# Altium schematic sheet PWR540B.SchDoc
size 431 x 279 mm; Date: Not shown in title block; ApprovedBy: Not shown in title block; CheckedBy: Not shown in title block; Author: Not shown in title block; CompanyName: Not shown in title block; Engineer: Not shown in title block; Organization: Not shown in title block; Address1: Not shown in title block; Address2: Not shown in title block; Address3: Not shown in title block; Address4: Not shown in title block; DocumentNumber: 1; Revision: Use project parameter SCH_Rev; SheetNumber: 1; SheetTotal: 2; PageSetup: Record=PageOptions¦CenterHorizontal=True¦CenterVertical=True¦PrintScale=0.64¦XCorrection=1.00¦YCorrection=1.00¦PrintKind=0¦BorderSize=5000000¦LeftOffset=0¦BottomOffset=0¦Orientation=2¦PaperLength=1000¦PaperWidth=1000¦Scale=100¦PaperSource=15¦PrintQuality=600¦MediaType=1¦DitherType=10¦PaperKind=Letter¦PrintScaleMode=1
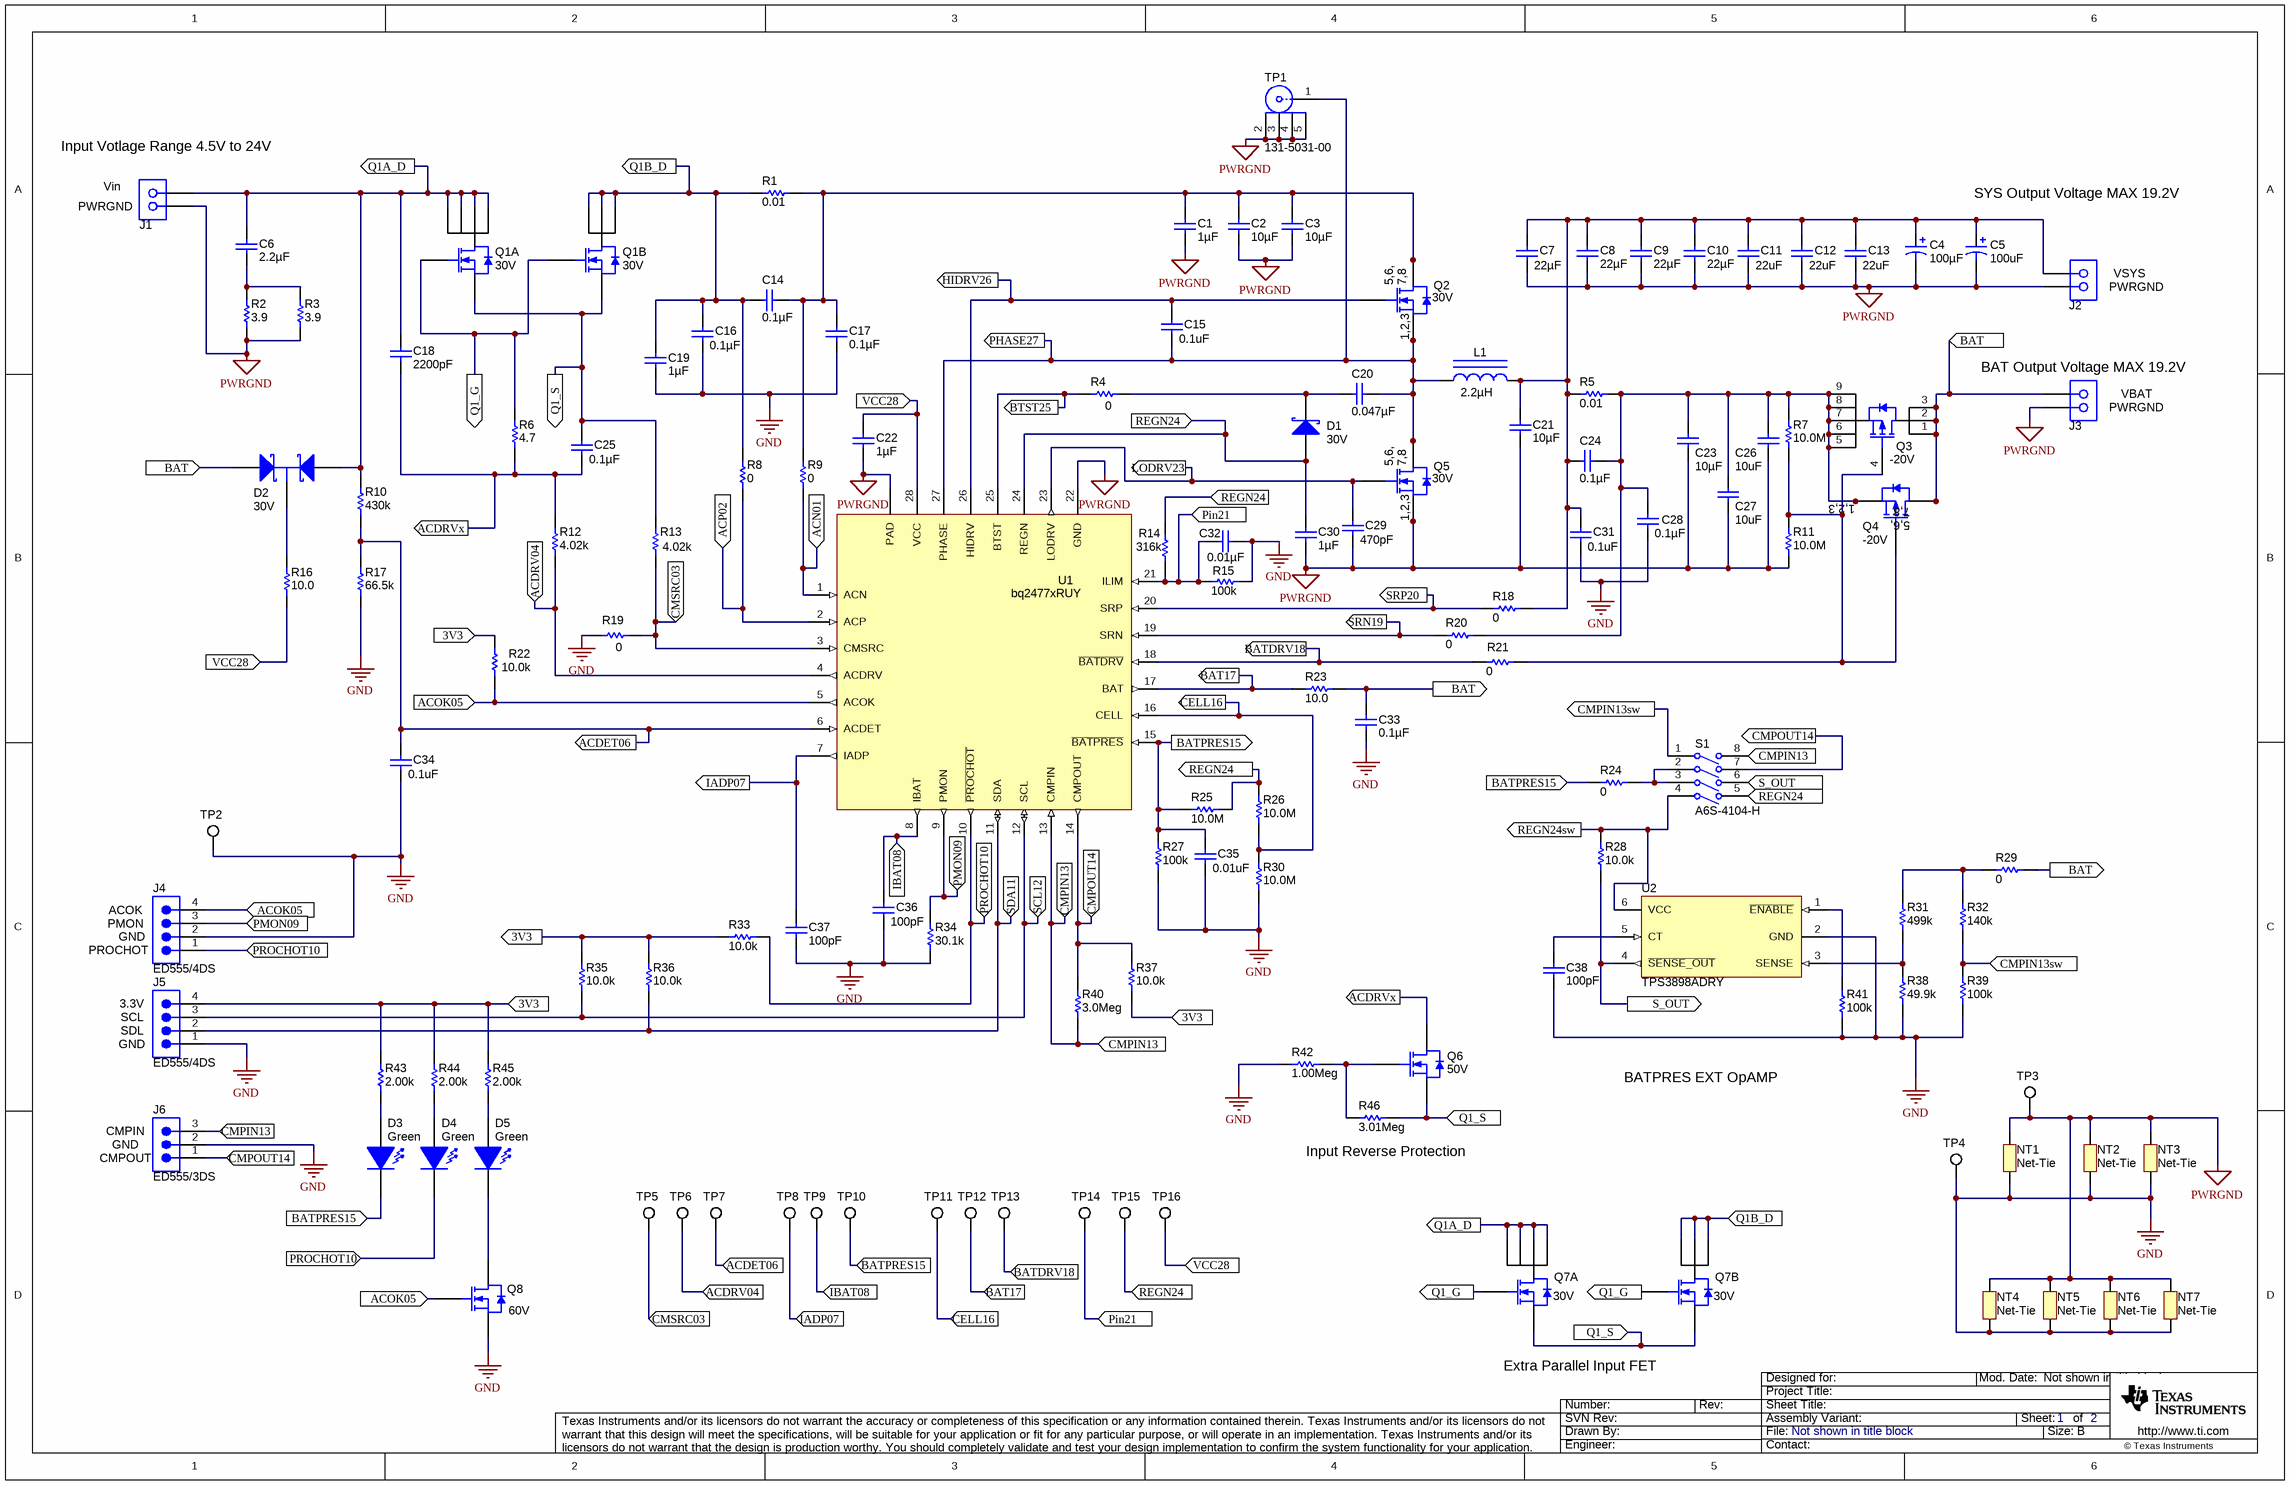
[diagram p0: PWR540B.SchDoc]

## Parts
C1  ValueDisplayed: 1µF  [0603L]  (hidden comment: GRM188R71E105KA12D)
C2  ValueDisplayed: 10µF  [1206]  (hidden comment: GRM31CR61E106KA12L)
C3  ValueDisplayed: 10µF  [1206]  (hidden comment: GRM31CR61E106KA12L)
C4  ValueDisplayed: 100µF  [SM_RADIAL_8MM]  (hidden comment: 20SVP100M)
C5  value 100uF  [SM_RADIAL_10AMM]  (hidden comment: 16SVP100M)
C6  ValueDisplayed: 2.2µF  [1206]  (hidden comment: GRM31MR71E225KA93L)
C7  ValueDisplayed: 22µF  [1210]  (hidden comment: GRM32ER61E226KE15L)
C8  ValueDisplayed: 22µF  [1210]  (hidden comment: GRM32ER61E226KE15L)
C9  ValueDisplayed: 22µF  [1210]  (hidden comment: GRM32ER61E226KE15L)
C10  ValueDisplayed: 22µF  [1210]  (hidden comment: GRM32ER61E226KE15L)
C11  value 22uF  [1210]  (hidden comment: GRM32ER61E226KE15L)
C12  value 22uF  [1210]  (hidden comment: GRM32ER61E226KE15L)
C13  value 22uF  [1210]  (hidden comment: GRM32ER61E226KE15L)
C14  ValueDisplayed: 0.1µF  [0603L]  (hidden comment: GRM188R71E104KA01D)
C15  value 0.1uF  [0603L]  (hidden comment: GRM188R71E104KA01D)
C16  ValueDisplayed: 0.1µF  [0603L]  (hidden comment: GRM188R71E104KA01D)
C17  ValueDisplayed: 0.1µF  [0603L]  (hidden comment: GRM188R71E104KA01D)
C18  ValueDisplayed: 2200pF  [0603L]  (hidden comment: GRM188R71E222KA01D)
C19  ValueDisplayed: 1µF  [0603L]  (hidden comment: GRM188R71E105KA12D)
C20  ValueDisplayed: 0.047µF  [0603L]  (hidden comment: GRM188R71E473KA01D)
C21  ValueDisplayed: 10µF  [1206]  (hidden comment: GRM31CR61E106KA12L)
C22  ValueDisplayed: 1µF  [0603L]  (hidden comment: GRM188R71E105KA12D)
C23  ValueDisplayed: 10µF  [1206]  (hidden comment: GRM31CR61E106KA12L)
C24  ValueDisplayed: 0.1µF  [0603L]  (hidden comment: GRM188R71E104KA01D)
C25  ValueDisplayed: 0.1µF  [0603L]  (hidden comment: GRM188R71E104KA01D)
C26  value 10uF  [1206]  (hidden comment: GRM31CR61E106KA12L)
C27  value 10uF  [1206]  (hidden comment: GRM31CR61E106KA12L)
C28  ValueDisplayed: 0.1µF  [0603L]  (hidden comment: GRM188R71E104KA01D)
C29  ValueDisplayed: 470pF  [0603L]  (hidden comment: GRM1885C1H471JA01D)
C30  ValueDisplayed: 1µF  [0603]  (hidden comment: GRM188R71E105KA12D)
C31  value 0.1uF  [0603L]  (hidden comment: GRM188R71E104KA01D)
C32  ValueDisplayed: 0.01µF  [0603]  (hidden comment: GRM188R71E103KA01D)
C33  ValueDisplayed: 0.1µF  [0603L]  (hidden comment: GRM188R71E104KA01D)
C34  value 0.1uF  [0603L]  (hidden comment: GRM188R71E104KA01D)
C35  value 0.01uF  [0603]  (hidden comment: GRM188R71E103KA01D)
C36  ValueDisplayed: 100pF  [0603L]  (hidden comment: C0603C101J5GAC)
C37  ValueDisplayed: 100pF  [0603L]  (hidden comment: C0603C101J5GAC)
C38  ValueDisplayed: 100pF  [0603L]  (hidden comment: C0603C101J5GAC)
D1  Value2: 30V  [SOT-23]  (hidden comment: BAT54-7-F)
D2  Value2: 30V  [SOT-23]  (hidden comment: BAT54C-7-F)
D3  value Green  [LED_LTST-C190]  (hidden comment: LTST-C190GKT)
D4  value Green  [LED_LTST-C190]  (hidden comment: LTST-C190GKT)
D5  value Green  [LED_LTST-C190]  (hidden comment: LTST-C190GKT)
J1  ED120/2DS  [CONN_ED120-2DS]  (value not drawn)
J2  ED120/2DS  [CONN_ED120-2DS]  (value not drawn)
J3  ED120/2DS  [CONN_ED120-2DS]  (value not drawn)
J4  ED555/4DS  [TERM_BLK_ED555-4DS]
J5  ED555/4DS  [TERM_BLK_ED555-4DS]
J6  ED555/3DS  [TERM_BLK_ED555-3DS]
L1  ValueDisplayed: 2.2µH  [IHLP-3232DZ]  (hidden comment: IHLP3232DZER2R2M01)
NT1  Net-Tie  [Net-Tie_20milWide_60milLong]  (net tie, no BOM)
NT2  Net-Tie  [Net-Tie_20milWide_60milLong]  (net tie, no BOM)
NT3  Net-Tie  [Net-Tie_20milWide_60milLong]  (net tie, no BOM)
NT4  Net-Tie  [Net-Tie_20milWide_60milLong]  (net tie, no BOM)
NT5  Net-Tie  [Net-Tie_20milWide_60milLong]  (net tie, no BOM)
NT6  Net-Tie  [Net-Tie_20milWide_60milLong]  (net tie, no BOM)
NT7  Net-Tie  [Net-Tie_20milWide_60milLong]  (net tie, no BOM)
Q1  value 30V  [TRANS_NexFET_Q3E]  (hidden comment: CSD87312Q3E)  (parts A,B of 2)
Q2  value 30V  [TRANS_NexFET_Q3]  (hidden comment: CSD17308Q3)
Q3  value -20V  [DQG0008A]  (hidden comment: CSD25401Q3)
Q4  value -20V  [PowerPAK_SO-8]  (hidden comment: SI7139DP-T1-GE3)
Q5  value 30V  [TRANS_NexFET_Q3]  (hidden comment: CSD17308Q3)
Q6  value 50V  [SOT-323]  (hidden comment: BSS138W-7-F)
Q7  value 30V  [TRANS_NexFET_Q3E]  (hidden comment: CSD87312Q3E)  (parts A,B of 2)
Q8  value 60V  [SOT-23L]  (hidden comment: 2N7002ET1G)
R1  value 0.01  [1206]  (hidden comment: WSLP1206R0100FEA)
R2  value 3.9  [1206]  (hidden comment: CRCW12063R90JNEA)
R3  value 3.9  [1206]  (hidden comment: CRCW12063R90JNEA)
R4  value 0  [0603L]  (hidden comment: CRCW06030000Z0EA)
R5  value 0.01  [1206]  (hidden comment: WSLP1206R0100FEA)
R6  value 4.7  [0603L]  (hidden comment: CRCW06034R70JNEA)
R7  value 10.0M  [0603L]  (hidden comment: CRCW060310M0JNEA)
R8  value 0  [0603L]  (hidden comment: CRCW06030000Z0EA)
R9  value 0  [0603L]  (hidden comment: CRCW06030000Z0EA)
R10  value 430k  [0603L]  (hidden comment: RC0603FR-07430KL)
R11  value 10.0M  [0603L]  (hidden comment: CRCW060310M0JNEA)
R12  value 4.02k  [0603L]  (hidden comment: CRCW06034K02FKEA)
R13  value 4.02k  [0603L]  (hidden comment: CRCW06034K02FKEA)
R14  value 316k  [0603]  (hidden comment: CRCW0603316KFKEA)
R15  value 100k  [0603]  (hidden comment: CRCW0603100KFKEA)
R16  value 10.0  [1206]  (hidden comment: CRCW120610R0FKEA)
R17  value 66.5k  [0603L]  (hidden comment: CRCW060366K5FKEA)
R18  value 0  [0603L]  (hidden comment: CRCW06030000Z0EA)
R19  value 0  [0603L]  (hidden comment: CRCW06030000Z0EA)
R20  value 0  [0603L]  (hidden comment: CRCW06030000Z0EA)
R21  value 0  [0603L]  (hidden comment: CRCW06030000Z0EA)
R22  value 10.0k  [0603L]  (hidden comment: CRCW060310K0FKEA)
R23  value 10.0  [0603]  (hidden comment: CRCW060310R0FKEA)
R24  value 0  [0805_HV]  (hidden comment: CRCW08050000Z0EA)
R25  value 10.0M  [0603L]  (hidden comment: CRCW060310M0JNEA)
R26  value 10.0M  [0603L]  (hidden comment: CRCW060310M0JNEA)
R27  value 100k  [0603]  (hidden comment: CRCW0603100KFKEA)
R28  value 10.0k  [0603L]  (hidden comment: CRCW060310K0FKEA)
R29  value 0  [0603L]  (hidden comment: CRCW06030000Z0EA)
R30  value 10.0M  [0603L]  (hidden comment: CRCW060310M0JNEA)
R31  value 499k  [0603L]  (hidden comment: CRCW0603499KFKEA)
R32  value 140k  [0603L]  (hidden comment: CRCW0603140KFKEA)
R33  value 10.0k  [0603L]  (hidden comment: CRCW060310K0FKEA)
R34  value 30.1k  [0603]  (hidden comment: CRCW060330K1FKEA)
R35  value 10.0k  [0603L]  (hidden comment: CRCW060310K0FKEA)
R36  value 10.0k  [0603L]  (hidden comment: CRCW060310K0FKEA)
R37  value 10.0k  [0603L]  (hidden comment: CRCW060310K0FKEA)
R38  value 49.9k  [0603L]  (hidden comment: CRCW060349K9FKEA)
R39  value 100k  [0603L]  (hidden comment: CRCW0603100KFKEA)
R40  value 3.0Meg  [0603L]  (hidden comment: CRCW06033M00JNEA)
R41  value 100k  [0603L]  (hidden comment: CRCW0603100KFKEA)
R42  value 1.00Meg  [0603L]  (hidden comment: CRCW06031M00FKEA)
R43  value 2.00k  [0603L]  (hidden comment: CRCW06032K00FKEA)
R44  value 2.00k  [0603L]  (hidden comment: CRCW06032K00FKEA)
R45  value 2.00k  [0603L]  (hidden comment: CRCW06032K00FKEA)
R46  value 3.01Meg  [0603L]  (hidden comment: CRCW06033M01FKEA)
S1  A6S-4104-H  [SW_A6S-4104-H]
TP1  131-5031-00  [Tek_131-5031-00]
TP2  5015  [Testpoint_Keystone_Miniature]  (value not drawn)
TP3  5015  [Testpoint_Keystone_Miniature]  (value not drawn)
TP4  5015  [Testpoint_Keystone_Miniature]  (value not drawn)
TP5  5015  [Testpoint_Keystone_Miniature]  (value not drawn)
TP6  5015  [Testpoint_Keystone_Miniature]  (value not drawn)
TP7  5015  [Testpoint_Keystone_Miniature]  (value not drawn)
TP8  5015  [Testpoint_Keystone_Miniature]  (value not drawn)
TP9  5015  [Testpoint_Keystone_Miniature]  (value not drawn)
TP10  5015  [Testpoint_Keystone_Miniature]  (value not drawn)
TP11  5015  [Testpoint_Keystone_Miniature]  (value not drawn)
TP12  5015  [Testpoint_Keystone_Miniature]  (value not drawn)
TP13  5015  [Testpoint_Keystone_Miniature]  (value not drawn)
TP14  5015  [Testpoint_Keystone_Miniature]  (value not drawn)
TP15  5015  [Testpoint_Keystone_Miniature]  (value not drawn)
TP16  5015  [Testpoint_Keystone_Miniature]  (value not drawn)
U1  bq2477xRUY  [RUY0028A]
U2  TPS3898ADRY  [DRY0006A]

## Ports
3V3, ACDET06, ACDRV04, ACDRVx, ACN01, ACOK05, ACP02, BAT, BAT17, BATDRV18, BATPRES15, BTST25, CELL16, CMPIN13, CMPIN13sw, CMPOUT14, CMSRC03, HIDRV26, IADP07, IBAT08, LODRV23, PHASE27, Pin21, PMON09, PROCHOT10, Q1_G, Q1_S, Q1A_D, Q1B_D, REGN24, REGN24sw, S_OUT, SCL12, SDA11, SRN19, SRP20, VCC28

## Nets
GND: C16.2 C17.2 C19.2 C28.2 C31.2 C32.1 C33.2 C34.2 C35.2 C36.2 C37.2 C38.2 J4.2 J5.1 J6.2 NT1.1 NT2.1 NT3.1 NT4.1 NT5.1 NT6.1 NT7.1 Q8.2(S) R15.2 R17.1 R19.2 R27.1 R30.1 R34.2 R38.1 R39.1 R41.1 R42.1 TP2.1 TP4.1 U2.2(GND)
PWRGND: C1.2 C2.2 C3.2 C4.2(-) C5.2(-) C7.2 C8.2 C9.2 C10.2 C11.2 C12.2 C13.2 C21.2 C22.2 C23.2 C26.2 C27.2 C29.2 C30.2 J1.2 J2.1 J3.1 NT1.2 NT2.2 NT3.2 NT4.2 NT5.2 NT6.2 NT7.2 Q5.1(S) Q5.2(S) Q5.3(S) R2.1 R3.1 R11.1 TP1.2 TP1.3 TP1.4 TP1.5 TP3.1 U1.22(GND) U1.29(PAD)
3V3: J5.4 R22.2 R33.2 R35.2 R36.2 R37.1 R43.1 R44.1 R45.2 ; port 3V3
ACDET06: C34.1 R10.1 R17.2 TP7.1 U1.6(ACDET) ; port ACDET06
ACDRV04: R12.1 TP6.1 U1.4(ACDRV) ; port ACDRV04
ACDRVx: C18.2 C25.2 Q6.3(D) R6.1 R12.2 ; port ACDRVx
ACN01: R9.1 U1.1(ACN) ; port ACN01
ACOK05: J4.4 Q8.1(G) R22.1 U1.5(ACOK) ; port ACOK05
ACP02: R8.1 U1.2(ACP) ; port ACP02
BAT: C33.1 D2.2(A2) J3.2 Q3.1(D) Q3.2(D) Q3.3(D) Q4.5(D) Q4.6(D) Q4.7(D) Q4.8(D) Q4.9(D) R23.2 R29.2 ; port BAT
BAT17: R23.1 TP12.1 U1.17(BAT) ; port BAT17
BATDRV18: R21.1 TP13.1 U1.18(~{BATDRV}) ; port BATDRV18
BATPRES15: C35.1 D3.2(K) R24.1 R25.2 R27.2 TP10.1 U1.15(~{BATPRES}) ; port BATPRES15
BTST25: R4.1 U1.25(BTST) ; port BTST25
CELL16: R26.1 R30.2 TP11.1 U1.16(CELL) ; port CELL16
CMPIN13: J6.3 R40.2 S1.8(B1) U1.13(CMPIN) ; port CMPIN13
CMPIN13sw: R32.1 R39.2 S1.1(A1) ; port CMPIN13sw
CMPOUT14: J6.1 R37.2 R40.1 S1.7(B2) U1.14(CMPOUT) ; port CMPOUT14
CMSRC03: R13.1 R19.1 TP5.1 U1.3(CMSRC) ; port CMSRC03
HIDRV26: C15.1 Q2.4(G) U1.26(HIDRV) ; port HIDRV26
IADP07: C37.1 TP8.1 U1.7(IADP) ; port IADP07
IBAT08: C36.1 TP9.1 U1.8(IBAT) ; port IBAT08
LODRV23: C29.1 Q5.4(G) U1.23(LODRV) ; port LODRV23
PHASE27: C15.2 C20.2 L1.1 Q2.1(S) Q2.2(S) Q2.3(S) Q5.5(D) Q5.6(D) Q5.7(D) Q5.8(D) Q5.9(D) TP1.1 U1.27(PHASE) ; port PHASE27
Pin21: C32.2 R14.1 R15.1 TP14.1 U1.21(ILIM) ; port Pin21
PMON09: J4.3 R34.1 U1.9(PMON) ; port PMON09
PROCHOT10: D4.2(K) J4.1 R33.1 U1.10(~{PROCHOT}) ; port PROCHOT10
Q1_G: Q1.5(G) Q7.5(G) R6.2 ; port Q1_G
Q1_S: C25.1 Q1.9(S) Q6.2(S) Q7.9(S) R13.2 R46.2 ; port Q1_S
Q1A_D: C6.1 C18.1 D2.1(A1) J1.1 Q1.1(D1) Q1.2(D1) Q1.3(D1) Q1.4(D1) Q7.1(D1) Q7.2(D1) Q7.3(D1) Q7.4(D1) R10.2 ; port Q1A_D
Q1B_D: C14.1 C16.1 C19.1 Q1.6(D2) Q1.7(D2) Q1.8(D2) Q7.6(D2) Q7.7(D2) Q7.8(D2) R1.1 R8.2 ; port Q1B_D
REGN24: C30.1 D1.1(A) R14.2 R25.1 R26.2 S1.5(B4) TP15.1 U1.24(REGN) ; port REGN24
REGN24sw: R28.2 S1.4(A4) U2.6(VCC) ; port REGN24sw
S_OUT: R28.1 S1.6(B3) U2.4(~{SENSE_OUT}) ; port S_OUT
SCL12: J5.3 R35.1 U1.12(SCL) ; port SCL12
SDA11: J5.2 R36.1 U1.11(SDA) ; port SDA11
SRN19: R20.1 U1.19(SRN) ; port SRN19
SRP20: R18.1 U1.20(SRP) ; port SRP20
VCC28: C22.1 R16.1 TP16.1 U1.28(VCC) ; port VCC28
NetC1_1: C1.1 C2.1 C3.1 C14.2 C17.1 Q2.5(D) Q2.6(D) Q2.7(D) Q2.8(D) Q2.9(D) R1.2 R9.2
NetC4_1: C4.1(+) C5.1(+) C7.1 C8.1 C9.1 C10.1 C11.1 C12.1 C13.1 C21.1 C24.1 C31.1 J2.2 L1.2 R5.1 R18.2
NetC6_2: C6.2 R2.2 R3.2
NetC20_1: C20.1 D1.3(K) R4.2
NetC23_1: C23.1 C24.2 C26.1 C27.1 C28.1 Q3.5(S) Q3.6(S) Q3.7(S) Q3.8(S) Q3.9(S) Q4.1(S) Q4.2(S) Q4.3(S) R5.2 R7.2 R20.2
NetC38_1: C38.1 U2.5(CT)
NetD2_3: D2.3(K) R16.2
NetD3_1: D3.1(A) R43.2
NetD4_1: D4.1(A) R44.2
NetD5_1: D5.1(A) R45.1
NetD5_2: D5.2(K) Q8.3(D)
NetQ3_4: Q3.4(G) Q4.4(G) R7.1 R11.2 R21.2
NetQ6_1: Q6.1(G) R42.2 R46.1
NetR24_2: R24.2 S1.2(A2) S1.3(A3)
NetR29_1: R29.1 R31.2 R32.2
NetR31_1: R31.1 R38.2 U2.3(SENSE)
NetR41_2: R41.2 U2.1(~{ENABLE})

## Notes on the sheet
- (near J1) Input Votlage Range 4.5V to 24V
- (near J1) PWRGND
- (near J1) Vin
- SYS Output Voltage MAX 19.2V
- (near J2) VSYS
- (near J2) PWRGND
- (near J3) BAT Output Voltage MAX 19.2V
- (near J3) PWRGND
- VBAT
- PROCHOT
- (near J4) ACOK
- (near J4) PMON
- (near J4) GND
- (near J5) 3.3V
- (near J5) SCL
- (near J5) SDL
- (near J5) GND
- BATPRES EXT OpAMP
- (near J6) CMPIN
- (near J6) CMPOUT
- (near J6) GND
- (near R46) Input Reverse Protection
- (near Q7) Extra Parallel Input FET

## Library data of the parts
C1 C19 C22 = GRM188R71E105KA12D: CAP, CERM, 1uF, 25V, +/-10%, X7R, 0603; Manufacturer: MuRata; Polarized: N; CompType: Capacitor; U/M: EA; Cap_F: 0.000001; Tolerance_%: 10; Value1: Unknown; VDC_V: 25; TaMin_C: -55; TaMax_C: 125; Cap_Case: 0603
C2 C3 C21 C23 = GRM31CR61E106KA12L: CAP, CERM, 10uF, 25V, +/-10%, X5R, 1206; Manufacturer: MuRata; Polarized: N; CompType: Capacitor; U/M: EA; Cap_F: 0.00001; Tolerance_%: 10; ESR_Ohm: 0.004; Value1: 0.004 ohm; VDC_V: 25; TaMin_C: -55; TaMax_C: 85
C4 = 20SVP100M: CAP, OS-CON, 100uF, 20V, +/-20%, 0.024 ohm, 8x10 SMD; Manufacturer: Sanyo; Polarized: Y; CompType: Capacitor; U/M: EA; Cap_F: 0.0001; Tolerance_%: 20; ESR_Ohm: 0.024; IRMS_A: 3.32; TaMin_C: -55; TaMax_C: 105; Cap_Case: 8.3x8.3x11.9
C5 = 16SVP100M: CAP, OS-CON, 100uF, 16V, +/-20%, 0.035 ohm, 10x10.3 SMD; Manufacturer: Sanyo; Polarized: Y; CompType: Capacitor; ValueDisplayed: 100µF; U/M: EA; Cap_F: 0.0001; Tolerance_%: 20; VDC_V: 16; Value2: DNP; ESR_Ohm: 0.035; IRMS_A: 2.67; TaMin_C: -55; TaMax_C: 105; Cap_Case: 10.3x10.3x7.9
C6 = GRM31MR71E225KA93L: CAP, CERM, 2.2uF, 25V, +/-10%, X7R, 1206; Manufacturer: MuRata; Polarized: N; CompType: Capacitor; U/M: EA; Cap_F: 0.0000022; Tolerance_%: 10; Value1: Unknown; VDC_V: 25; TaMin_C: -55; TaMax_C: 125; Cap_Case: 1210
C7-C10 = GRM32ER61E226KE15L: CAP, CERM, 22uF, 25V, +/-10%, X5R, 1210; Manufacturer: MuRata; Polarized: N; CompType: Capacitor; U/M: EA; Cap_F: 0.000022; Tolerance_%: 10; ESR_Ohm: 0.002; Value1: 0.002 ohm; VDC_V: 25; IRMS_A: 3.67; TaMin_C: -55; TaMax_C: 85
C11-C13 = GRM32ER61E226KE15L: CAP, CERM, 22uF, 25V, +/-10%, X5R, 1210; Manufacturer: MuRata; Polarized: N; CompType: Capacitor; ValueDisplayed: 22µF; U/M: EA; Cap_F: 0.000022; Tolerance_%: 10; ESR_Ohm: 0.002; Value1: 0.002 ohm; VDC_V: 25; Value2: DNP; IRMS_A: 3.67; TaMin_C: -55; TaMax_C: 85
C14 C16 C17 C24 C25 C28 C31 C33 = GRM188R71E104KA01D: CAP, CERM, 0.1uF, 25V, +/-10%, X7R, 0603; Manufacturer: MuRata; Polarized: N; CompType: Capacitor; U/M: EA; Cap_F: 0.0000001; Tolerance_%: 10; Value1: Unknown; VDC_V: 25; TaMin_C: -55; TaMax_C: 125; Cap_Case: 0603
C15 = GRM188R71E104KA01D: CAP, CERM, 0.1uF, 25V, +/-10%, X7R, 0603; Manufacturer: MuRata; Polarized: N; CompType: Capacitor; ValueDisplayed: 0.1µF; U/M: EA; Cap_F: 0.0000001; Tolerance_%: 10; Value1: Unknown; VDC_V: 25; Value2: DPM; TaMin_C: -55; TaMax_C: 125; Cap_Case: 0603
C18 = GRM188R71E222KA01D: CAP, CERM, 2200pF, 25V, +/-10%, X7R, 0603; Manufacturer: MuRata; Polarized: N; CompType: Capacitor; U/M: EA; Cap_F: 0.0000000022; Tolerance_%: 10; Value1: Unknown; VDC_V: 25; TaMin_C: -55; TaMax_C: 125; Cap_Case: 0603
C20 = GRM188R71E473KA01D: CAP, CERM, 0.047uF, 25V, +/-10%, X7R, 0603; Manufacturer: MuRata; Polarized: N; CompType: Capacitor; U/M: EA; Cap_F: 0.000000047; Tolerance_%: 10; Value1: Unknown; VDC_V: 25; TaMin_C: -55; TaMax_C: 125; Cap_Case: 0603
C26 C27 = GRM31CR61E106KA12L: CAP, CERM, 10uF, 25V, +/-10%, X5R, 1206; Manufacturer: MuRata; Polarized: N; CompType: Capacitor; ValueDisplayed: DNP; U/M: EA; Cap_F: 0.00001; Tolerance_%: 10; ESR_Ohm: 0.004; Value1: 0.004 ohm; VDC_V: 25; TaMin_C: -55; TaMax_C: 85
C29 = GRM1885C1H471JA01D: CAP, CERM, 470pF, 50V, +/-5%, C0G/NP0, 0603; Manufacturer: MuRata; Polarized: N; CompType: Capacitor; U/M: EA; Cap_F: 0.00000000047; Tolerance_%: 5; Value1: Unknown; VDC_V: 50; TaMin_C: -55; TaMax_C: 125; Cap_Case: 0603
C30 = GRM188R71E105KA12D: CAP, CERM, 1uF, 25V, +/-10%, X7R, 0603; Manufacturer: MuRata; Polarized: N; CompType: Capacitor; U/M: EA; Cap_F: 0.000001; Tolerance_%: 10; Value1: Unknown; VDC_V: 25; TaMin_C: -55; TaMax_C: 125
C32 = GRM188R71E103KA01D: CAP, CERM, 0.01uF, 25V, +/-10%, X7R, 0603; Manufacturer: MuRata; Polarized: N; CompType: Capacitor; U/M: EA; Cap_F: 0.00000001; Tolerance_%: 10; Value1: Unknown; VDC_V: 25; TaMin_C: -55; TaMax_C: 125
C34 = GRM188R71E104KA01D: CAP, CERM, 0.1uF, 25V, +/-10%, X7R, 0603; Manufacturer: MuRata; Polarized: N; CompType: Capacitor; U/M: EA; Cap_F: 0.0000001; Tolerance_%: 10; Value1: Unknown; VDC_V: 25; Value2: DNP; TaMin_C: -55; TaMax_C: 125; Cap_Case: 0603
C35 = GRM188R71E103KA01D: CAP, CERM, 0.01uF, 25V, +/-10%, X7R, 0603; Manufacturer: MuRata; Polarized: N; CompType: Capacitor; ValueDisplayed: 0.01µF; U/M: EA; Cap_F: 0.00000001; Tolerance_%: 10; Value1: Unknown; VDC_V: 25; Value2: DNP; TaMin_C: -55; TaMax_C: 125
C36-C38 = C0603C101J5GAC: CAP, CERM, 100pF, 50V, +/-5%, C0G/NP0, 0603; Manufacturer: Kemet; Polarized: N; CompType: Capacitor; U/M: EA; Cap_F: 0.0000000001; Tolerance_%: 5; Value1: Unknown; VDC_V: 50; TaMin_C: -55; TaMax_C: 125; Cap_Case: 0603
D1 = BAT54-7-F: Diode, Schottky, 30V, 0.2A, SOT-23; Manufacturer: Diodes Inc.; Value: 0.65V; U/M: EA; Vf_V: 0.65; Io_A: 0.2; Vr_V: 30; TJmax_C: 125
D2 = BAT54C-7-F: Diode, Schottky, 30V, 0.2A, SOT-23; Manufacturer: Diodes Inc.; Value: 0.65V; U/M: EA; Vf_V: 0.65; Io_A: 0.2; Vr_V: 30; TJmax_C: 125
D3-D5 = LTST-C190GKT: LED, Green, SMD; Manufacturer: Lite-On; Vf_V: 2.1; Value2: 2.1V; Io_A: 0.02; Power_TotalModule: 0.1; Value1: 0.1W; U/M: EA
J1-J3 = ED120/2DS: TERMINAL BLOCK 5.08MM VERT 2POS; Manufacturer: On-Shore Technology, Inc.; U/M: EA
J4 J5 = ED555/4DS: Terminal Block, 6A, 3.5mm Pitch, 4-Pos, TH; Manufacturer: On-Shore Technology, Inc.; SymbolCreator: a0412235; CompType: Connector; U/M: EA
J6 = ED555/3DS: Terminal Block, 6A, 3.5mm Pitch, 3-Pos, TH; Manufacturer: On-Shore Technology, Inc.; SymbolCreator: a0412235; CompType: Connector; U/M: EA
L1 = IHLP3232DZER2R2M01: Inductor, Shielded, Powdered Iron, 2.2 µH, 10.5 A, 0.0137 ohm, SMD; Manufacturer: Vishay-Dale; Value: 2.2uH; Ind_H: 2.2E-6; Imax_A: 10.5; Irms: 10.5A @ 40C rise; Isat: 23A @ 20% inductance drop; DCR_ohm: 0.0137; Value2: 10.5A; AEC Category: Q200
NT1-NT7 = Net-Tie: Single point connection between nets.; SymbolCreator: codlsc
Q1 = CSD87312Q3E: MOSFET, N-CH, 30V, 27A, SON 3.3x3.3mm; Manufacturer: Texas Instruments; Alternate Manufacturer: None; SymbolCreator: a0411947; U/M: EA; ChType: N; VdsMax_V: 30; Value1: ? ohm; Value2: 6.3 nC; QgTyp_nC: 6.3; Vgs_V: 1; IdsMax_A: 27
Q2 Q5 = CSD17308Q3: MOSFET, N-CH, 30V, 47A, SON 3.3x3.3mm; Manufacturer: Texas Instruments; Alternate Manufacturer: None; U/M: EA; ChType: N; VdsMax_V: 30; Value1: 0.0094 ohm; Rdson45_Ohm: 0.0094; Value2: 3.9 nC; QgTyp_nC: 3.9; Vgs_V: 10; IdsMax_A: 47
Q3 = CSD25401Q3: MOSFET, P-CH, -20 V, -60 A, VSON-CLIP-8; Manufacturer: Texas Instruments; Alternate Manufacturer: None; SymbolCreator: a0799628; U/M: EA; ChType: P; Value1: 0.0088 ohm; Rdson45_ohm: 0.0088; Value2: 8.8 nC; QgTyp_nC: 8.8; Vgs_V: -12; AEC Category: Q101
Q4 = SI7141DP-T1-GE3: MOSFET, P-CH, -20V, 60A, PowerPAK SO-8; Manufacturer: Vishay-Semiconductor; Alternate Manufacturer: None; U/M: EA; ChType: P; VdsMax_V: -20; Value1: 0.0019 ohm; Rdson45_Ohm: 0.0019; Value2: DNP; QgTyp_nC: 400; Vgs_V: 20; IdsMax_A: 60
Q6 = BSS138W-7-F: MOSFET, N-CH, 50V, 0.2A, SOT-323; Manufacturer: Diodes Inc.; Alternate Manufacturer: None; U/M: EA; ChType: N; VdsMax_V: 50; Value1: 3.5 ohm; Rdson45_Ohm: 3.5; Value2: ? nC; Vgs_V: 1.5; IdsMax_A: 0.2
Q7 = CSD87312Q3E: MOSFET, N-CH, 30V, 27A, SON 3.3x3.3mm; Manufacturer: Texas Instruments; Alternate Manufacturer: None; SymbolCreator: a0411947; U/M: EA; ChType: N; VdsMax_V: 30; Value1: ? ohm; Value2: DNP; QgTyp_nC: 6.3; Vgs_V: 1; IdsMax_A: 27
Q8 = 2N7002ET1G: MOSFET, N-CH, 60V, 0.26A, SOT-23; Manufacturer: ON Semiconductor; Alternate Manufacturer: None; U/M: EA; ChType: N; VdsMax_V: 60; Value1: 3 ohm; Rdson45_Ohm: 3; Value2: 0.81 nC; QgTyp_nC: 0.81; Vgs_V: 20; IdsMax_A: 0.26
R1 R5 = WSLP1206R0100FEA: RES, 0.01 ohm, 1%, 1W, 1206; Manufacturer: Vishay-Dale; CompType: Resistor; Value_Code: R010; Tolerance_%: 1; TempCo: 75 ppm/C; EIA_Code: E96; U/M: EA
R2 R3 = CRCW12063R90JNEA: RES, 3.9 ohm, 5%, 0.25W, 1206; Manufacturer: Vishay-Dale; CompType: Resistor; Value_Code: 3R90; Tolerance_%: 5; Power_W: 0.25; VDC_V: 200; TempCo: 200 ppm/C; EIA_Code: E24; U/M: EA
R4 R8 R9 R18 R20 R21 R29 = CRCW06030000Z0EA: RES, 0 ohm, 5%, 0.1W, 0603; Manufacturer: Vishay-Dale; CompType: Resistor; Value_Code: 0000; Tolerance_%: 5; Power_W: 0.1; VDC_V: 75; TempCo: 200 ppm/C; EIA_Code: E24; U/M: EA
R6 = CRCW06034R70JNEA: RES, 4.7 ohm, 5%, 0.1W, 0603; Manufacturer: Vishay-Dale; CompType: Resistor; Value_Code: 4R70; Tolerance_%: 5; Power_W: 0.1; VDC_V: 75; TempCo: 200 ppm/C; EIA_Code: E24; U/M: EA
R7 R11 R25 = CRCW060310M0JNEA: RES, 10Meg ohm, 5%, 0.1W, 0603; Manufacturer: Vishay-Dale; CompType: Resistor; Res_ohm: 10000000; Value_Code: 10M0; Tolerance_%: 5; Power_W: 0.1; VDC_V: 75; TempCo: 200 ppm/C; EIA_Code: E24; U/M: EA
R10 = RC0603FR-07430KL: RES, 430k ohm, 1%, 0.1W, 0603; Manufacturer: Yageo America; CompType: Resistor; Res_ohm: 430000; Tolerance_%: 1; Power_W: 0.1; VDC_V: 150; TempCo: 200 ppm/C; U/M: EA
R12 R13 = CRCW06034K02FKEA: RES, 4.02k ohm, 1%, 0.1W, 0603; Manufacturer: Vishay-Dale; CompType: Resistor; Res_ohm: 4020; Value_Code: 4k02; Tolerance_%: 1; Power_W: 0.1; VDC_V: 75; TempCo: 100 ppm/C; EIA_Code: E96; U/M: EA
R14 = CRCW0603316KFKEA: RES, 316k ohm, 1%, 0.1W, 0603; Manufacturer: Vishay-Dale; CompType: Resistor; Res_ohm: 316000; Tolerance_%: 1; Power_W: 0.1; VDC_V: 75; TempCo: 100 ppm/C; EIA_Code: E96; U/M: EA
R15 R27 R39 R41 = CRCW0603100KFKEA: RES, 100k ohm, 1%, 0.1W, 0603; Manufacturer: Vishay-Dale; CompType: Resistor; Res_ohm: 100000; Tolerance_%: 1; Power_W: 0.1; VDC_V: 75; TempCo: 100 ppm/C; EIA_Code: E96; U/M: EA
R16 = CRCW120610R0FKEA: RES, 10.0 ohm, 1%, 0.25W, 1206; Manufacturer: Vishay-Dale; CompType: Resistor; Res_ohm: 10; Value_Code: 10R0; Tolerance_%: 1; Power_W: 0.25; VDC_V: 200; TempCo: 100 ppm/C; EIA_Code: E96; U/M: EA
R17 = CRCW060366K5FKEA: RES, 66.5k ohm, 1%, 0.1W, 0603; Manufacturer: Vishay-Dale; CompType: Resistor; Res_ohm: 66500; Value_Code: 66k5; Tolerance_%: 1; Power_W: 0.1; VDC_V: 75; TempCo: 100 ppm/C; EIA_Code: E96; U/M: EA
R19 = CRCW06030000Z0EA: RES, 0 ohm, 5%, 0.1W, 0603; Manufacturer: Vishay-Dale; CompType: Resistor; Value_Code: 0000; Tolerance_%: 5; Power_W: 0.1; Value2: DNI; VDC_V: 75; TempCo: 200 ppm/C; EIA_Code: E24; U/M: EA
R22 R28 R33 R35-R37 = CRCW060310K0FKEA: RES, 10.0k ohm, 1%, 0.1W, 0603; Manufacturer: Vishay-Dale; CompType: Resistor; Res_ohm: 10000; Value_Code: 10k0; Tolerance_%: 1; Power_W: 0.1; VDC_V: 75; TempCo: 100 ppm/C; EIA_Code: E96; U/M: EA
R23 = CRCW060310R0FKEA: RES, 10.0 ohm, 1%, 0.1W, 0603; Manufacturer: Vishay-Dale; CompType: Resistor; Res_ohm: 10; Value_Code: 10R0; Tolerance_%: 1; Power_W: 0.1; VDC_V: 75; TempCo: 100 ppm/C; EIA_Code: E96; U/M: EA
R24 = CRCW08050000Z0EA: RES, 0 ohm, 5%, 0.125W, 0805; Manufacturer: Vishay-Dale; CompType: Resistor; Value_Code: 0000; Tolerance_%: 5; Power_W: 0.125; VDC_V: 150; TempCo: 200 ppm/C; EIA_Code: E24; U/M: EA
R26 R30 = CRCW060310M0JNEA: RES, 10Meg ohm, 5%, 0.1W, 0603; Manufacturer: Vishay-Dale; CompType: Resistor; Res_ohm: 10000000; Value_Code: 10M0; Tolerance_%: 5; Power_W: 0.1; Value2: DNP; VDC_V: 75; TempCo: 200 ppm/C; EIA_Code: E24; U/M: EA
R31 = CRCW0603499KFKEA: RES, 499k ohm, 1%, 0.1W, 0603; Manufacturer: Vishay-Dale; CompType: Resistor; Res_ohm: 499000; Tolerance_%: 1; Power_W: 0.1; VDC_V: 75; TempCo: 100 ppm/C; EIA_Code: E96; U/M: EA
R32 = CRCW0603140KFKEA: RES, 140k ohm, 1%, 0.1W, 0603; Manufacturer: Vishay-Dale; CompType: Resistor; Res_ohm: 140000; Tolerance_%: 1; Power_W: 0.1; VDC_V: 75; TempCo: 100 ppm/C; EIA_Code: E96; U/M: EA
R34 = CRCW060330K1FKEA: RES, 30.1k ohm, 1%, 0.1W, 0603; Manufacturer: Vishay-Dale; CompType: Resistor; Res_ohm: 30100; Value_Code: 30k1; Tolerance_%: 1; Power_W: 0.1; VDC_V: 75; TempCo: 100 ppm/C; EIA_Code: E96; U/M: EA
R38 = CRCW060349K9FKEA: RES, 49.9k ohm, 1%, 0.1W, 0603; Manufacturer: Vishay-Dale; CompType: Resistor; Res_ohm: 49900; Value_Code: 49k9; Tolerance_%: 1; Power_W: 0.1; VDC_V: 75; TempCo: 100 ppm/C; EIA_Code: E96; U/M: EA
R40 = CRCW06033M00JNEA: RES, 3.0Meg ohm, 5%, 0.1W, 0603; Manufacturer: Vishay-Dale; CompType: Resistor; Res_ohm: 3000000; Value_Code: 3M00; Tolerance_%: 5; Power_W: 0.1; VDC_V: 75; TempCo: 200 ppm/C; EIA_Code: E24; U/M: EA
R42 = CRCW06031M00FKEA: RES, 1.00Meg ohm, 1%, 0.1W, 0603; Manufacturer: Vishay-Dale; CompType: Resistor; Res_ohm: 1000000; Value_Code: 1M00; Tolerance_%: 1; Power_W: 0.1; VDC_V: 75; TempCo: 100 ppm/C; EIA_Code: E96; U/M: EA
R43-R45 = CRCW06032K00FKEA: RES, 2.00k ohm, 1%, 0.1W, 0603; Manufacturer: Vishay-Dale; CompType: Resistor; Res_ohm: 2000; Value_Code: 2k00; Tolerance_%: 1; Power_W: 0.1; VDC_V: 75; TempCo: 100 ppm/C; EIA_Code: E96; U/M: EA
R46 = CRCW06033M01FKEA: RES, 3.01Meg ohm, 1%, 0.1W, 0603; Manufacturer: Vishay-Dale; CompType: Resistor; Res_ohm: 3010000; Value_Code: 3M01; Tolerance_%: 1; Power_W: 0.1; VDC_V: 75; TempCo: 100 ppm/C; EIA_Code: E96; U/M: EA
S1 = A6S-4104-H: DIP Switch, 4 position slide actuator, SPST, SMD; Manufacturer: Omron Electronic Components; VDC_V: 24; SwitchFunction: Off-On; PositionCount: 4; CurrentRating_mA: 25
TP1 = 131-5031-00: Compact Probe Tip Circuit Board Test Points, TH, 25 per; Manufacturer: Tektronix
TP2-TP16 = 5015: Test Point, Miniature, SMT; Manufacturer: Keystone; CompType: Test Point Loop
U1 = bq24770RUY: NVDC Battery Charge Controller with SMBus, RUY0028A; Alternate Manufacturer: None; Manufacturer: Texas Instruments; SymbolCreator: a0411947; CompType: IC; U/M: EA
U2 = TPS3898ADRY: Single-Channel, Adjustable Supervisory Circuit in Ultra-Small Package, DRY0006A; Alternate Manufacturer: None; Manufacturer: Texas Instruments; SymbolCreator: a0411947; CompType: IC; U/M: EA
